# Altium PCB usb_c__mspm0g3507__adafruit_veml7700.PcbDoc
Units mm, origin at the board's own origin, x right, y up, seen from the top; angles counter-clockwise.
Board outline 92 x 60 mm, 2 copper layers (Top, Bottom), stack 0 mm thick; 33 components, 29 nets, 178 pads, 49 vias.
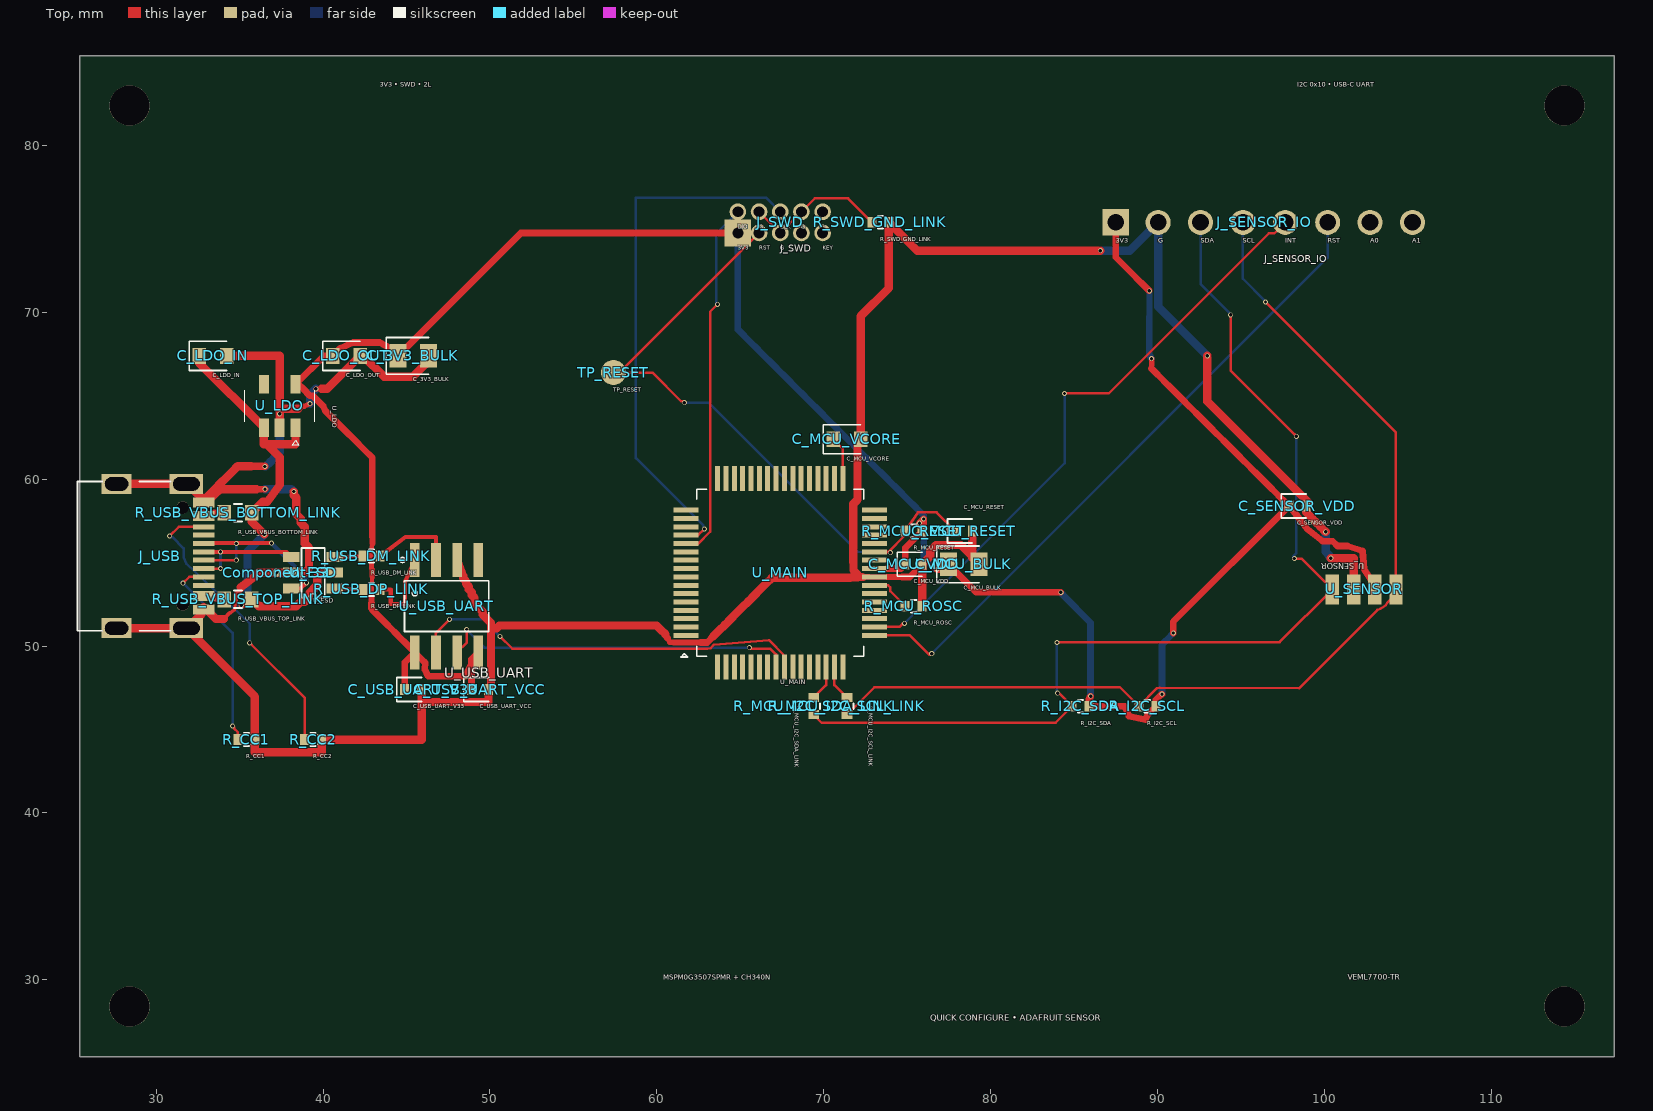
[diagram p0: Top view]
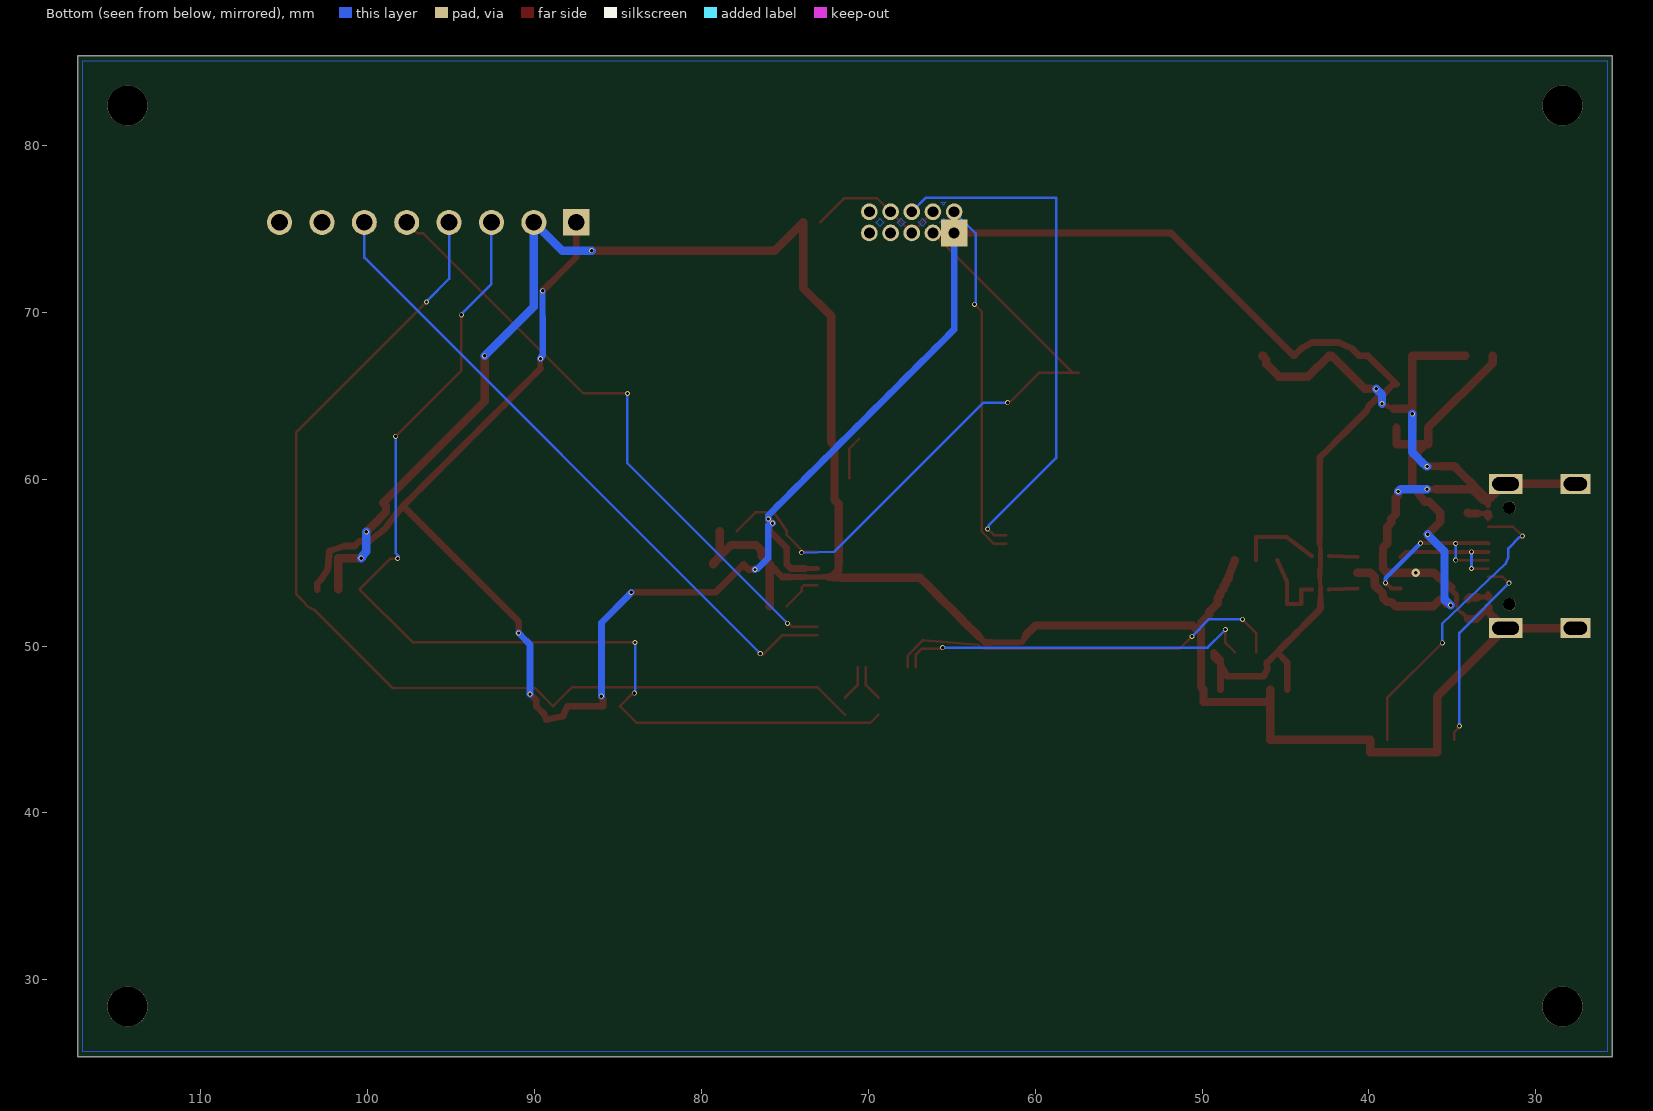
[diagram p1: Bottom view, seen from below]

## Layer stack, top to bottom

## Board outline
25.4,85.4 117.4,85.4 117.4,25.4 25.4,25.4

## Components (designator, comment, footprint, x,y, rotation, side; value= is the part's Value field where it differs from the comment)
C_3V3_BULK "" TSCIRCUIT-2.8500x1.4000mm 45.4,67.4 r0 top
C_LDO_IN "" TSCIRCUIT-2.4500x0.9500mm 33.4,67.4 r0 top
C_LDO_OUT "" TSCIRCUIT-2.4500x0.9500mm 41.4,67.4 r0 top
C_MCU_BULK "" TSCIRCUIT-2.8500x1.4000mm 78.4,54.9 r0 top
C_MCU_RESET "" TSCIRCUIT-1.5600x0.6400mm 78.4,56.9 r0 top
C_MCU_VCORE "" TSCIRCUIT-2.4500x0.9500mm 71.4,62.4 r0 top
C_MCU_VDD "" TSCIRCUIT-1.5600x0.6400mm 75.4,54.9 r0 top
C_SENSOR_VDD "" TSCIRCUIT-1.5600x0.6400mm 98.4,58.4 r0 top
C_USB_UART_V33 "" TSCIRCUIT-1.5600x0.6400mm 45.4,47.4 r0 top
C_USB_UART_VCC "" TSCIRCUIT-1.5600x0.6400mm 49.4,47.4 r0 top
Component-33 "" TSCIRCUIT-0.5000x0.5000mm 37.2,54.4 r0 top
J_SENSOR_IO "" TSCIRCUIT-19.2800x1.5000mm 96.4,75.4 r0 top
J_SWD "" TSCIRCUIT-6.0800x2.2700mm 67.4,75.4 r0 top
J_USB "" TSCIRCUIT-6.7732x9.8502mm 30.113,55.4 r90 top
R_CC1 "" TSCIRCUIT-1.5600x0.6400mm 35.4,44.4 r0 top
R_CC2 "" TSCIRCUIT-1.5600x0.6400mm 39.4,44.4 r0 top
R_I2C_SCL "" TSCIRCUIT-1.5600x0.6400mm 89.4,46.4 r0 top
R_I2C_SDA "" TSCIRCUIT-1.5600x0.6400mm 85.4,46.4 r0 top
R_MCU_I2C_SCL_LINK "" TSCIRCUIT-0.6400x1.5600mm 71.4,46.4 r270 top
R_MCU_I2C_SDA_LINK "" TSCIRCUIT-0.6400x1.5600mm 69.4,46.4 r270 top
R_MCU_RESET "" TSCIRCUIT-1.5600x0.6400mm 75.4,56.9 r0 top
R_MCU_ROSC "" TSCIRCUIT-1.5600x0.6400mm 75.4,52.4 r0 top
R_SWD_GND_LINK "" TSCIRCUIT-1.5600x0.6400mm 73.4,75.4 r0 top
R_USB_DM_LINK "" TSCIRCUIT-1.5600x0.6400mm 42.9,55.4 r0 top
R_USB_DP_LINK "" TSCIRCUIT-1.5600x0.6400mm 42.9,53.4 r0 top
R_USB_VBUS_BOTTOM_LINK "" TSCIRCUIT-2.4500x0.9500mm 34.9,58 r0 top
R_USB_VBUS_TOP_LINK "" TSCIRCUIT-2.4500x0.9500mm 34.9,52.8 r0 top
TP_RESET "" TSCIRCUIT-1.5000x1.5000mm 57.4,66.4 r0 top
U_ESD "" TSCIRCUIT-3.6000x2.5000mm 39.4,54.4 r0 top
U_LDO "" TSCIRCUIT-2.5000x3.7000mm 37.4,64.4 r270 top
U_MAIN "" TSCIRCUIT-12.8000x12.8000mm 67.4,54.4 r0 top
U_SENSOR "" TSCIRCUIT-4.6100x1.8000mm 102.4,53.4 r0 top
U_USB_UART "" TSCIRCUIT-4.3840x7.5712mm 47.4,52.4 r0 top

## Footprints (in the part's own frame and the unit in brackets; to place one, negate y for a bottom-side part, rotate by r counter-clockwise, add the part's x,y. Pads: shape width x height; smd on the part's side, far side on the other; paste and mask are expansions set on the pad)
TSCIRCUIT-0.5000x0.5000mm [mm]
TSCIRCUIT-0.6400x1.5600mm [mm]
  rect 0.54x0.64 smd: 1(-0.51,0) 2(0.51,0)
  silkscreen extent -0.15,-0.38 0.15,0.38
TSCIRCUIT-1.5000x1.5000mm [mm]
  round 1.5 smd: 1(0,0)
TSCIRCUIT-1.5600x0.6400mm [mm]
  rect 0.54x0.64 smd: 1(-0.51,0) 2(0.51,0)
  silkscreen extent -0.98,-0.72 0.51,0.72
TSCIRCUIT-2.4500x0.9500mm [mm]
  rect 0.8x0.95 smd: 1(-0.825,0) 2(0.825,0)
  silkscreen extent -1.42,-0.87 0.82,0.87
TSCIRCUIT-2.5000x3.7000mm [mm]
  rect 1.1x0.6 smd: 1(1.3,0.95) 2(1.3,0) 3(1.3,-0.95) 4(-1.3,-0.95) 5(-1.3,0.95)
  silkscreen extent -0.95,-2.1 2.35,2.1
TSCIRCUIT-2.8500x1.4000mm [mm]
  rect 1.025x1.4 smd: 1(-0.913,0) 2(0.913,0)
  silkscreen extent -1.63,-1.1 0.91,1.1
TSCIRCUIT-3.6000x2.5000mm [mm]
  rect 1x0.6 smd: 1(-1.3,-0.95) 2(-1.3,0) 3(-1.3,0.95) 4(1.3,0.95) 5(1.3,0) 6(1.3,-0.95)
  silkscreen extent -0.7,-1.49 0.7,1.49
TSCIRCUIT-4.3840x7.5712mm [mm]
  rect 0.574x2.036 smd: 1(-1.905,2.768) 2(-0.635,2.768) 3(0.635,2.768) 4(1.905,2.768) 5(1.905,-2.768) 6(0.635,-2.768) 7(-0.635,-2.768) 8(-1.905,-2.768)
  silkscreen extent -2.79,-1.52 2.53,2.92
TSCIRCUIT-4.6100x1.8000mm [mm]
  rect 0.8x1.8 smd: 1(1.905,0) 2(0.635,0) 3(-0.635,0) 4(-1.905,0)
TSCIRCUIT-6.0800x2.2700mm [mm]
  rect 1.6x1.6 hole 0.65: 1(-2.54,-0.635)
  round 1 hole 0.65: 2(-2.54,0.635) 3(-1.27,0.635) 4(0,0.635) 5(1.27,0.635) 6(2.54,0.635) 7(2.54,-0.635) 8(1.27,-0.635) 9(0,-0.635) 10(-1.27,-0.635)
TSCIRCUIT-6.7732x9.8502mm [mm]
  rect 0.3x1.3 smd: 1(-3.35,-2.737) 2(-3.05,-2.737) 3(-2.55,-2.737) 4(-2.25,-2.737) 5(-1.75,-2.737) 6(-1.25,-2.737) 7(-0.75,-2.737) 8(-0.25,-2.737) 9(0.25,-2.737) 10(0.75,-2.737) 11(1.25,-2.737) 12(1.75,-2.737) 13(2.55,-2.737) 14(2.25,-2.737) 15(3.35,-2.737) 16(3.05,-2.737)
  rect 1.2x2 hole 0.8 slot 1.6 at 90 deg: 17(-4.325,-1.693) 18(4.325,-1.693)
  rect 1.2x1.8 hole 0.8 slot 1.4 at 90 deg: 19(4.325,2.487) 20(-4.325,2.487)
  round 0.75 hole 0.75 unplated: NPTH-1(-2.9,-1.468) NPTH-2(2.9,-1.468)
  silkscreen extent -4.47,-0.75 4.47,4.83
TSCIRCUIT-12.8000x12.8000mm [mm]
  rect 1.5x0.3 smd: 1(-5.65,-3.75) 2(-5.65,-3.25) 3(-5.65,-2.75) 4(-5.65,-2.25) 5(-5.65,-1.75) 6(-5.65,-1.25) 7(-5.65,-0.75) 8(-5.65,-0.25) 9(-5.65,0.25) 10(-5.65,0.75) 11(-5.65,1.25) 12(-5.65,1.75) 13(-5.65,2.25) 14(-5.65,2.75) 15(-5.65,3.25) 16(-5.65,3.75) 33(5.65,3.75) 34(5.65,3.25) 35(5.65,2.75) 36(5.65,2.25) 37(5.65,1.75) 38(5.65,1.25) 39(5.65,0.75) 40(5.65,0.25) 41(5.65,-0.25) 42(5.65,-0.75) 43(5.65,-1.25) 44(5.65,-1.75) 45(5.65,-2.25) 46(5.65,-2.75) 47(5.65,-3.25) 48(5.65,-3.75)
  rect 0.3x1.5 smd: 17(-3.75,5.65) 18(-3.25,5.65) 19(-2.75,5.65) 20(-2.25,5.65) 21(-1.75,5.65) 22(-1.25,5.65) 23(-0.75,5.65) 24(-0.25,5.65) 25(0.25,5.65) 26(0.75,5.65) 27(1.25,5.65) 28(1.75,5.65) 29(2.25,5.65) 30(2.75,5.65) 31(3.25,5.65) 32(3.75,5.65) 49(3.75,-5.65) 50(3.25,-5.65) 51(2.75,-5.65) 52(2.25,-5.65) 53(1.75,-5.65) 54(1.25,-5.65) 55(0.75,-5.65) 56(0.25,-5.65) 57(-0.25,-5.65) 58(-0.75,-5.65) 59(-1.25,-5.65) 60(-1.75,-5.65) 61(-2.25,-5.65) 62(-2.75,-5.65) 63(-3.25,-5.65) 64(-3.75,-5.65)
  silkscreen extent -5.95,-5.05 5,5
TSCIRCUIT-19.2800x1.5000mm [mm]
  rect 1.6x1.6 hole 1: 1(-8.89,0)
  round 1.5 hole 1: 2(-6.35,0) 3(-3.81,0) 4(-1.27,0) 5(1.27,0) 6(3.81,0) 7(6.35,0) 8(8.89,0)

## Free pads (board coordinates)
  round 2.4 hole 2.4 unplated: NPTH-3(28.4,28.4) NPTH-4(114.4,28.4) NPTH-5(28.4,82.4) NPTH-6(114.4,82.4)

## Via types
v1: diameter 0.3, hole 0.2, Top to Bottom, 48 vias
v2: diameter 0.5, hole 0.2, Top to Bottom, 1 vias

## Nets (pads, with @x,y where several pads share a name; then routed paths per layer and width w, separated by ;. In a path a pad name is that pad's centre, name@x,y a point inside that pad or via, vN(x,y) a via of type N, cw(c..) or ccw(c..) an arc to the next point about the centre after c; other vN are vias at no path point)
".J_SWD > .pin2 to .U_MAIN > .pin12": J_SWD.2 U_MAIN.12 | length 21.7
  Top w0.15: U_MAIN.12 62.494,56.15 63.204,56.859 63.204,70.054 v1(63.641,70.491)
  Bottom w0.15: v1(63.641,70.491) 63.572,70.56 63.572,70.569 63.572,74.747 J_SWD.2
".J_SWD > .pin4 to .U_MAIN > .pin13": J_SWD.4 U_MAIN.13 | length 31.8
  Top w0.15: U_MAIN.13 62.479,56.65 v1(62.847,57.018)
  Bottom w0.15: v1(62.847,57.018) 62.797,57.068 62.797,57.224 58.746,61.275 58.746,76.869 66.566,76.869 J_SWD.4
".U_MAIN > .pin42 to .R_MCU_ROSC > .pin1": R_MCU_ROSC.1 U_MAIN.42 | length 2.5
  Top w0.15: U_MAIN.42 73.86,53.65 73.994,53.516 73.994,53.296 R_MCU_ROSC.1
GND: C_3V3_BULK.2 C_LDO_IN.2 C_LDO_OUT.2 C_MCU_BULK.2 C_MCU_RESET.2 C_MCU_VCORE.2 C_MCU_VDD.2 C_SENSOR_VDD.2 C_USB_UART_V33.2 C_USB_UART_VCC.2 J_SENSOR_IO.2 J_USB.1 J_USB.2 J_USB.15 J_USB.16 J_USB.17 J_USB.18 J_USB.19 J_USB.20 R_CC1.2 R_CC2.2 R_MCU_ROSC.2 R_SWD_GND_LINK.2 U_ESD.2 U_LDO.2 U_MAIN.41 U_SENSOR.3 U_USB_UART.3 | length 208
  Top w0.2: 34.4,51.977 34.7,52.2 34.749,52.692
  Top w0.25: 34.055,51.627 34.4,51.977
  Top w0.275: J_USB.2 J_USB.1@33.09,52.109
  Top w0.3: J_USB.1@32.699,51.9 J_USB.1 J_USB.1@32.849,52.2 ; J_USB.15@32.699,58.9 J_USB.15 ; J_USB.16 J_USB.16@32.999,58.6 ; J_USB.16@32.849,58.6 J_USB.15 ; J_USB.15@32.999,58.9 J_USB.15 ; 34.749,52.692 34.754,53.057 ; v1(39.568,65.421) 39.907,65.421 ; U_MAIN.41@72.675,54.15 72.769,54.15 72.863,54.15 72.956,54.15 U_MAIN.41 ; U_MAIN.41@72.712,54.16 U_MAIN.41 ; U_MAIN.41@73.8,54.15 73.706,54.15 73.612,54.15 73.519,54.15 73.425,54.15 73.331,54.15 73.237,54.15 73.144,54.15 U_MAIN.41
  Top w0.312: 34.754,53.057 35.09,53.392 35.072,53.525 ; 38.513,64.225 38.866,64.38 v1(39.219,64.535)
  Top w0.325: J_USB.16 J_USB.16@32.849,58.6 ; J_USB.16@32.999,58.6 J_USB.15@33.168,58.769 ; 60.642,50.48 60.775,50.244 61.002,50.224
  Top w0.329: 72.3,54.157 72.402,54.155 U_MAIN.41@72.675,54.15
  Top w0.346: U_MAIN.41@72.386,54.129 U_MAIN.41@72.712,54.16
  Top w0.35: 61.002,50.224 61.407,50.224 61.811,50.224 62.215,50.224 62.619,50.224
  Top w0.375: U_MAIN.41@73.8,54.15 74.253,54.15 74.707,54.15
  Top w0.4: 36.012,59.405 36.453,59.405 36.516,59.408 v1(36.517,59.41) ; 37.2,54.4 U_ESD.2@37.6,54.4 ; 62.619,50.224 63.024,50.224 63.376,50.576 ; 74.707,54.15 75.16,54.15 75.41,54.4 75.66,54.65 C_MCU_VDD.2
  Top w0.425: 60.509,50.717 60.642,50.48
  Top w0.437: 71.59,54.097 72.059,54.097 U_MAIN.41@72.386,54.129
  Top w0.45: 35.695,60.776 36.102,60.772 v1(36.509,60.769)
  Top w0.475: 33.572,51.627 34.055,51.627 ; 72.129,54.16 72.3,54.157
  Top w0.5: J_USB.20 J_USB.17 ; J_USB.19 J_USB.18 31.874,59.725 32.474,59.125 32.699,58.9 ; 32.699,51.9 32.474,51.675 31.874,51.075 J_USB.17 ; J_USB.1@32.849,52.2 J_USB.2 ; 32.999,58.9 33.188,59.089 33.527,59.428 33.866,59.767 34.204,60.105 34.543,60.444 34.882,60.783 35.289,60.779 35.695,60.776 ; J_USB.1@33.09,52.109 33.572,51.627 ; J_USB.15@33.168,58.769 33.486,59.087 33.805,59.405 34.246,59.405 34.687,59.405 35.129,59.405 35.57,59.405 36.012,59.405 ; C_LDO_IN.2 37.4,67.4 U_LDO.2 ; 35.072,53.525 35.418,53.795 35.763,54.064 36.1,54.4 36.467,54.4 36.833,54.4 37.2,54.4 38.9,54.4 39.15,54.65 39.15,55.9 38.9,56.15 38.9,57.15 38.65,57.4 38.65,57.65 38.4,57.9 38.4,58.9 38.248,59.052 v1(38.248,59.274) ; v1(37.4,63.925) 37.4,62.85 U_LDO.2 ; 38.513,64.225 37.4,64.225 U_LDO.2 ; 39.907,65.421 40.246,65.421 40.576,65.751 40.906,66.081 41.236,66.41 41.565,66.74 41.895,67.07 C_LDO_OUT.2 42.4,67.4 43.65,66.15 45.4,66.15 46.15,66.9 46.15,67.15 46.4,67.4 C_3V3_BULK.2 ; U_USB_UART.3 48.4,54.2 48.4,54.067 48.567,53.9 48.567,53.733 48.733,53.567 48.733,53.4 48.9,53.233 48.9,53.067 49.067,52.9 49.067,52.567 49.567,52.067 49.567,51.9 50.067,51.4 C_USB_UART_VCC.2@50.067,47.567 ; 60.509,50.717 60.262,50.964 59.993,51.233 50.567,51.233 50.4,51.067 50.233,51.067 50.067,50.9 C_USB_UART_VCC.2@50.067,47.567 ; 63.376,50.576 63.728,50.928 64.08,51.28 64.432,51.632 64.784,51.984 65.137,52.337 65.489,52.689 65.841,53.041 66.193,53.393 66.545,53.745 66.897,54.097 67.367,54.097 67.836,54.097 68.305,54.097 68.774,54.097 69.243,54.097 69.713,54.097 70.182,54.097 70.651,54.097 71.12,54.097 71.59,54.097 ; 72.129,54.16 71.957,54.351 71.786,54.541 71.787,55.037 71.775,55.025 71.775,58.525 72.025,58.775 72.025,62.025 72.225,62.225 C_MCU_VCORE.2 72.225,62.892 72.225,63.384 72.225,63.876 72.225,64.368 72.225,64.86 72.225,65.352 72.225,65.844 72.225,66.336 72.225,66.828 72.225,67.32 72.225,67.812 72.225,68.303 72.225,68.795 72.225,69.287 72.225,69.779 73.91,71.464 R_SWD_GND_LINK.2 75.608,73.702 v1(86.586,73.702) ; R_MCU_ROSC.2 C_MCU_VDD.2 75.9,54.9 76.4,55.4 76.4,55.733 76.733,56.067 78.233,56.067 79.313,54.988 C_MCU_BULK.2 78.91,55.303 C_MCU_RESET.2 ; v1(92.997,67.4) 92.997,64.667 94.565,63.098 99.087,58.577 C_SENSOR_VDD.2 98.91,58.03 99.198,57.742 99.486,57.454 99.774,57.166 100.062,56.878 v1(100.086,56.854) ; v1(100.398,55.276) 101.765,55.276 U_SENSOR.3 ; J_USB.17 35.91,46.971 R_CC1.2 35.91,43.65 39.91,43.65 R_CC2.2 40.41,44.4 40.91,44.4 45.91,44.4 C_USB_UART_V33.2 45.91,46.65 49.91,46.65 C_USB_UART_VCC.2 ; C_USB_UART_VCC.2 C_USB_UART_VCC.2@49.91,47.41 ; C_USB_UART_VCC.2 C_USB_UART_VCC.2@49.91,47.41 ; C_USB_UART_VCC.2@49.91,47.41 C_USB_UART_VCC.2@50.067,47.567 ; C_USB_UART_VCC.2@49.91,47.41 C_USB_UART_VCC.2@50.067,47.567
  Bottom w0.5: v1(36.509,60.769) 36.543,60.763 36.551,60.763 36.834,61.046 37.117,61.329 37.4,61.612 37.4,61.951 37.4,62.29 v1(37.4,63.925) ; v1(36.517,59.41) 36.913,59.409 37.308,59.408 37.704,59.408 38.1,59.407 38.219,59.287 38.235,59.287 v1(38.248,59.274) ; v1(39.219,64.535) 39.219,64.804 39.219,65.072 39.544,65.397 v1(39.568,65.421) ; v1(86.586,73.702) 88.352,73.702 J_SENSOR_IO.2 90.05,74.941 90.05,74.481 90.05,74.022 90.05,73.563 90.05,73.103 90.05,72.644 90.05,72.184 90.05,71.725 90.05,71.266 90.05,70.806 90.05,70.347 90.377,70.02 90.705,69.692 91.032,69.365 91.36,69.037 91.687,68.71 92.015,68.382 92.342,68.055 92.669,67.728 v1(92.997,67.4) ; v1(100.086,56.854) 100.086,56.457 100.086,56.061 100.086,55.664 100.305,55.446 100.305,55.369 v1(100.398,55.276)
MAIN_RESET: C_MCU_RESET.1 J_SWD.10 R_MCU_RESET.1 TP_RESET.1 U_MAIN.38 | length 40.8
  Top w0.15: v1(61.65,64.593) 61.562,64.681 61.452,64.681 59.733,66.4 TP_RESET.1 57.765,66.4 J_SWD.10 ; v1(74,55.6) U_MAIN.38 73.889,55.65 74.889,56.651 R_MCU_RESET.1@74.889,56.899 ; R_MCU_RESET.1 75.65,58.014 76.776,58.014 C_MCU_RESET.1
  Bottom w0.15: v1(61.65,64.593) 63.11,64.593 72.053,55.65 v1(74,55.6)
MCU_I2C_SCL_LOCAL: R_MCU_I2C_SCL_LINK.1 U_MAIN.50 | length 2.2
  Top w0.15: U_MAIN.50 70.65,47.66 R_MCU_I2C_SCL_LINK.1
MCU_I2C_SDA_LOCAL: R_MCU_I2C_SDA_LINK.1 U_MAIN.51 | length 2.2
  Top w0.15: R_MCU_I2C_SDA_LINK.1 70.15,47.66 U_MAIN.51
MSPM0_VCORE: C_MCU_VCORE.1 U_MAIN.32 | length 2.6
  Top w0.15: C_MCU_VCORE.1 71.15,61.825 U_MAIN.32
SENSOR_ADDR0: J_SENSOR_IO.7
SENSOR_ADDR1: J_SENSOR_IO.8
SENSOR_INT: J_SENSOR_IO.5 U_MAIN.47 | length 37.1
  Top w0.15: U_MAIN.47 74.548,51.15 74.726,51.328 74.804,51.328 v1(74.847,51.371) ; v1(84.441,65.147) 87.09,65.149 96.692,74.748 97.018,74.748 J_SENSOR_IO.5
  Bottom w0.15: v1(74.847,51.371) 84.439,60.963 v1(84.441,65.147) v1(84.441,65.147)
SENSOR_RESET: J_SENSOR_IO.6 U_MAIN.48 | length 39.6
  Top w0.15: U_MAIN.48 75.165,50.65 76.321,49.494 76.42,49.494 v1(76.48,49.554)
  Bottom w0.15: v1(76.48,49.554) 100.21,73.284 J_SENSOR_IO.6
SENSOR_SCL: J_SENSOR_IO.4 R_I2C_SCL.1 R_MCU_I2C_SCL_LINK.2 U_SENSOR.1 | length 62.9
  Top w0.15: R_MCU_I2C_SCL_LINK.2 73.047,47.537 87.611,47.537 87.753,47.537 R_I2C_SCL.1 89.981,47.491 90.132,47.509 98.516,47.491 103.194,52.168 103.37,52.241 103.705,52.439 103.788,52.614 104.305,53.132 U_SENSOR.1 104.305,62.805 v1(96.485,70.625)
  Bottom w0.15: J_SENSOR_IO.4 95.13,72.022 96.454,70.698 96.454,70.656 v1(96.485,70.625)
SENSOR_SDA: J_SENSOR_IO.3 R_I2C_SDA.1 R_MCU_I2C_SDA_LINK.2 U_SENSOR.4 | length 63.8
  Top w0.15: R_MCU_I2C_SDA_LINK.2 69.881,45.409 83.899,45.409 R_I2C_SDA.1 84.105,47.185 v1(84.022,47.185) ; v1(83.984,50.217) 84.005,50.238 84.055,50.238 97.333,50.238 U_SENSOR.4 98.646,55.249 v1(98.213,55.249) ; v1(94.394,69.855) 94.394,66.534 98.232,62.696 98.232,62.675 v1(98.332,62.574)
  Bottom w0.15: v1(83.984,50.217) 83.984,47.223 83.987,47.22 v1(84.022,47.185) ; J_SENSOR_IO.3 92.59,71.7 94.393,69.897 94.393,69.856 v1(94.394,69.855) ; v1(98.213,55.249) 98.154,55.308 98.154,55.401 98.332,55.579 v1(98.332,62.574)
swd-ground-1-to-2: J_SWD.3 J_SWD.5 J_SWD.9 R_SWD_GND_LINK.1 | length 8.8
  Top w0.15: J_SWD.3 J_SWD.9 J_SWD.5 69.481,76.846 71.471,76.846 71.471,76.819 R_SWD_GND_LINK.1
UART_MSP_RX: U_MAIN.57 U_USB_UART.6 | length 21.5
  Top w0.15: U_USB_UART.6 48.6,50.197 v1(48.6,51) ; v1(65.55,49.909) 65.552,49.907 65.569,49.907 65.622,49.853 66.797,49.853 67.15,49.5 U_MAIN.57
  Bottom w0.15: v1(48.6,51) 48.684,50.916 48.684,50.893 49.668,49.909 v1(65.55,49.909)
UART_MSP_TX: U_MAIN.56 U_USB_UART.7 | length 24.3
  Top w0.15: U_USB_UART.7 46.765,50.794 v1(47.579,51.608) ; v1(50.603,50.587) 50.612,50.578 51.347,49.843 63.025,49.843 63.221,49.873 63.428,50.096 66.714,50.362 67.65,49.427 U_MAIN.56
  Bottom w0.15: v1(47.579,51.608) 47.588,51.617 47.781,51.617 49.573,51.617 v1(50.603,50.587)
usb-dm-device: R_USB_DM_LINK.1 U_ESD.4 | length 1.7
  Top w0.25: U_ESD.4 R_USB_DM_LINK.1
usb-dm-port-tie: J_USB.7 J_USB.9 U_ESD.3 | length 8.4
  Top w0.15: J_USB.7 v1(33.85,54.65) ; J_USB.9 v1(33.85,55.65)
  Top w0.25: J_USB.9 34.67,55.65 37.8,55.65 U_ESD.3
  Bottom w0.15: v1(33.85,54.65) v1(33.85,55.65)
usb-dm-uart: R_USB_DM_LINK.2 U_USB_UART.2 | length 5.1
  Top w0.25: R_USB_DM_LINK.2 44.95,56.55 46.765,56.55 U_USB_UART.2
usb-dp-device: R_USB_DP_LINK.1 U_ESD.6 | length 1.7
  Top w0.25: U_ESD.6 R_USB_DP_LINK.1
usb-dp-port-tie: J_USB.8 J_USB.10 U_ESD.1 | length 13.3
  Top w0.15: J_USB.8 v1(34.8,55.15) ; J_USB.10 v1(34.8,56.15)
  Top w0.25: J_USB.10 32.874,56.175 v1(36.91,56.175) ; U_ESD.1 38.647,53.45 38.967,53.77 38.97,53.77 v1(39,53.8)
  Bottom w0.15: v1(34.8,55.15) v1(34.8,56.15)
  Bottom w0.25: v1(36.91,56.175) 36.899,56.169 39,54.068 v1(39,53.8)
usb-dp-uart: R_USB_DP_LINK.2 U_USB_UART.1 | length 5.1
  Top w0.25: R_USB_DP_LINK.2 44.05,53.4 44.05,52.53 44.9,52.53 44.9,53.85 U_USB_UART.1
USB_CC1: J_USB.6 R_CC1.1 | length 12.3
  Top w0.15: v1(31.606,53.779) 31.978,54.15 J_USB.6 ; v1(34.58,45.219) 34.671,45.128 34.671,45.059 34.89,44.84 R_CC1.1
  Bottom w0.15: v1(31.606,53.779) 31.539,53.846 31.535,53.846 34.58,50.801 v1(34.58,45.219)
USB_CC2: J_USB.12 R_CC2.1 | length 17.9
  Top w0.15: v1(30.8,56.6) 31.35,57.15 J_USB.12 ; v1(35.6,50.2) 35.715,50.085 38.89,46.91 R_CC2.1
  Bottom w0.15: v1(30.8,56.6) 30.868,56.532 30.975,56.532 31.643,55.864 31.643,55.31 31.8,54.95 35.6,51.352 v1(35.6,50.2)
USB_VBUS_BOTTOM_LOCAL: J_USB.13 J_USB.14 R_USB_VBUS_BOTTOM_LINK.1 | length 1.5
  Top w0.3: J_USB.14 J_USB.14@32.849,57.8 ; J_USB.13 32.927,57.95 33.005,57.95 33.083,57.95 33.161,57.95 33.239,57.95 33.317,57.95 33.394,57.95 33.472,57.95 33.499,57.95
  Top w0.475: J_USB.13@32.849,57.8 J_USB.13 ; 33.499,57.95 R_USB_VBUS_BOTTOM_LINK.1@33.762,57.95
  Top w0.5: R_USB_VBUS_BOTTOM_LINK.1@33.762,57.95 34.025,57.95 R_USB_VBUS_BOTTOM_LINK.1
USB_VBUS_TOP_LOCAL: J_USB.3 J_USB.4 R_USB_VBUS_TOP_LINK.1 | length 1.6
  Top w0.3: J_USB.4 32.849,53 J_USB.3 32.944,52.958 33.032,52.939 33.499,52.939
  Top w0.5: 33.499,52.939 33.675,52.939 33.936,52.939 R_USB_VBUS_TOP_LINK.1
VBUS5: C_LDO_IN.1 R_USB_VBUS_BOTTOM_LINK.2 R_USB_VBUS_TOP_LINK.2 U_ESD.5 U_LDO.1 U_LDO.3 | length 30
  Top w0.325: v1(35.099,52.457) 35.382,52.457 R_USB_VBUS_TOP_LINK.2
  Top w0.5: C_LDO_IN.1 32.575,66.975 U_LDO.3 ; R_USB_VBUS_TOP_LINK.2 35.981,52.544 35.9,52.625 35.9,52.65 36.15,52.4 38.4,52.4 38.65,52.65 38.9,52.65 39.15,52.9 39.15,53.15 39.65,53.65 39.65,54.15 39.9,54.4 U_ESD.5 ; v1(36.48,56.698) 35.725,57.453 R_USB_VBUS_BOTTOM_LINK.2 36.375,58.65 36.65,58.65 37.397,59.665 37.397,61.329 36.454,62.272 36.452,62.686 U_LDO.3 ; U_LDO.1 38.35,62.1 36.45,62.1 U_LDO.3
  Bottom w0.5: v1(35.099,52.457) 35.387,52.745 35.468,52.745 35.468,55.686 v1(36.48,56.698)
VCC_3V3: C_3V3_BULK.1 C_LDO_OUT.1 C_MCU_BULK.1 C_MCU_VDD.1 C_SENSOR_VDD.1 C_USB_UART_V33.1 C_USB_UART_VCC.1 J_SENSOR_IO.1 J_SWD.1 R_I2C_SCL.2 R_I2C_SDA.2 R_MCU_RESET.2 U_LDO.5 U_MAIN.40 U_SENSOR.2 U_USB_UART.5 U_USB_UART.8 | length 157.2
  Top w0.25: 42.9,53.525 42.924,53.86 42.949,54.194
  Top w0.262: 42.9,55.65 42.925,55.907 42.95,56.163
  Top w0.275: 42.9,52.9 42.9,53.212 42.9,53.525 ; 42.9,54.983 42.9,55.317 42.9,55.65
  Top w0.3: U_MAIN.40 73.15,54.65 73.25,54.65 73.35,54.65 73.45,54.65 73.55,54.65 73.65,54.65 73.75,54.65 U_MAIN.40@73.8,54.65
  Top w0.312: 42.9,54.983 42.9,54.65 42.949,54.588 42.949,54.194
  Top w0.325: 89.653,66.637 89.654,66.934 v1(89.655,67.232)
  Top w0.363: 42.95,56.163 42.951,56.557
  Top w0.387: 42.9,52.587 42.9,52.9
  Top w0.4: 42.9,52.587 42.9,52.275 42.947,52.225 42.958,52.169 43.24,51.887 43.522,51.605 43.804,51.323 44.086,51.041 44.368,50.759 44.649,50.478 44.931,50.196 45.213,49.914 U_USB_UART.8 ; 42.951,56.557 42.951,56.951 42.951,57.345 42.952,57.739 42.952,58.133 42.952,58.527 42.953,58.921 42.953,59.314 42.953,59.708 42.954,60.102 42.954,60.496 42.954,60.89 42.955,61.284 42.824,61.418 42.556,61.686 42.289,61.953 42.021,62.221 41.754,62.489 41.486,62.756 41.218,63.024 40.951,63.291 40.683,63.559 40.416,63.827 40.148,64.094 40,64.4 39.4,65 39.2,65 38.81,65.432 38.542,65.7 U_LDO.5 40.05,67.4 C_LDO_OUT.1 40.795,67.622 41.016,67.843 41.8,68.2 43.4,68.2 44.047,67.841 44.267,67.62 C_3V3_BULK.1 51.853,74.765 J_SWD.1 ; C_USB_UART_V33.1 44.89,49.027 U_USB_UART.8 ; C_USB_UART_VCC.1 48.89,49.217 U_USB_UART.5 49.305,49.345 49.093,49.129 48.881,48.912 48.5,48.2 46.3,48.2 46.1,48.6 46.115,49.012 45.908,49.219 45.702,49.425 U_USB_UART.8 ; U_MAIN.40@73.8,54.65 73.85,54.65 74.64,54.65 C_MCU_VDD.1 74.89,55.88 R_MCU_RESET.2 ; v1(75.75,57.375) 75.994,57.614 75.91,57.53 75.91,57.215 R_MCU_RESET.2 ; v1(76,57.62) 76,57.305 76,56.99 R_MCU_RESET.2 ; v1(76.791,54.592) 77.18,54.592 77.334,54.746 C_MCU_BULK.1 79.162,53.226 v1(84.215,53.226) ; v1(86,47) 85.96,46.96 85.96,46.879 85.91,46.829 R_I2C_SDA.2 86.264,46.4 86.619,46.4 86.973,46.4 87.327,46.4 87.682,46.4 88.036,46.4 88.3,45.8 89.3,45.6 89.482,45.972 ; J_SENSOR_IO.1 87.51,75.051 87.51,74.702 87.51,74.353 87.51,74.005 87.51,73.656 87.51,73.307 87.778,73.038 88.047,72.77 88.315,72.502 88.583,72.233 88.852,71.965 89.12,71.697 89.389,71.428 v1(89.523,71.294) ; 89.653,66.637 89.928,66.362 90.202,66.088 90.477,65.813 90.751,65.539 91.026,65.264 91.3,64.99 91.575,64.715 91.85,64.44 92.124,64.166 92.399,63.891 92.673,63.617 92.948,63.342 93.222,63.068 93.497,62.793 93.771,62.519 94.046,62.244 94.321,61.969 94.595,61.695 94.87,61.42 95.144,61.146 95.419,60.871 95.693,60.597 95.968,60.322 96.243,60.047 96.517,59.773 96.792,59.498 97.066,59.224 97.341,58.949 97.615,58.675 C_SENSOR_VDD.1 ; v1(90.276,47.119) 90.177,47.039 89.91,46.772 R_I2C_SCL.2 89.696,46.186 89.482,45.972 ; v1(90.958,50.79) 90.958,51.468 C_SENSOR_VDD.1 ; U_SENSOR.2 103.035,53.768 102.755,54.048 102.4,54.6 102.3,55.7 101.4,56 100.795,56.008 100.515,56.288 100.258,56.288 99.9,56.3 99,57 98.238,57.99 98.064,58.195 C_SENSOR_VDD.1 ; 89.482,45.972 89.474,45.972 89.482,45.972
  Bottom w0.35: 89.523,69.747 89.523,70.134 89.523,70.52 89.523,70.907 v1(89.523,71.294)
  Bottom w0.4: J_SWD.1 64.86,74.379 64.86,73.993 64.86,73.608 64.86,73.222 64.86,72.836 64.86,72.45 64.86,72.065 64.86,71.679 64.86,71.293 64.86,70.907 64.86,70.521 64.86,70.136 64.86,69.75 64.86,69.364 64.86,68.978 65.138,68.7 65.417,68.421 65.695,68.143 65.974,67.864 66.252,67.586 66.531,67.308 66.809,67.029 67.088,66.751 67.366,66.472 67.644,66.194 67.923,65.915 68.201,65.637 68.48,65.358 68.758,65.08 69.037,64.802 69.315,64.523 69.594,64.245 69.872,63.966 70.151,63.688 70.429,63.409 70.707,63.131 70.986,62.852 71.264,62.574 71.543,62.295 71.821,62.017 72.1,61.739 72.378,61.46 72.657,61.182 72.935,60.903 73.213,60.625 73.492,60.346 73.77,60.068 74.049,59.789 74.327,59.511 74.606,59.233 74.884,58.954 75.163,58.676 75.441,58.397 75.719,58.119 75.998,57.84 75.998,57.622 v1(76,57.62) ; v1(75.75,57.375) 76,57.23 76,56.84 76,56.45 76,56.06 76,55.67 76,55.28 76.214,55.066 76.428,54.851 76.643,54.637 76.745,54.637 v1(76.791,54.592) ; v1(84.215,53.226) 84.341,53.1 84.341,53.062 86,51.402 v1(86,47) ; 89.523,69.747 89.523,69.36 89.523,68.973 89.523,68.587 89.523,68.2 89.523,67.813 89.523,67.426 89.616,67.333 89.616,67.271 v1(89.655,67.232) ; v1(90.276,47.119) 90.276,50.096 90.835,50.655 90.835,50.667 v1(90.958,50.79)
pads on no net: J_SWD.6 J_SWD.7 J_SWD.8 J_USB.5 J_USB.11 J_USB.NPTH-1 J_USB.NPTH-2 U_LDO.4 U_MAIN.1 U_MAIN.2 U_MAIN.3 U_MAIN.4 U_MAIN.5 U_MAIN.6 U_MAIN.7 U_MAIN.8 U_MAIN.9 U_MAIN.10 U_MAIN.11 U_MAIN.14 U_MAIN.15 U_MAIN.16 U_MAIN.17 U_MAIN.18 U_MAIN.19 U_MAIN.20 U_MAIN.21 U_MAIN.22 U_MAIN.23 U_MAIN.24 U_MAIN.25 U_MAIN.26 U_MAIN.27 U_MAIN.28 U_MAIN.29 U_MAIN.30 U_MAIN.31 U_MAIN.33 U_MAIN.34 U_MAIN.35 U_MAIN.36 U_MAIN.37 U_MAIN.39 U_MAIN.43 U_MAIN.44 U_MAIN.45 U_MAIN.46 U_MAIN.49 U_MAIN.52 U_MAIN.53 U_MAIN.54 U_MAIN.55 U_MAIN.58 U_MAIN.59 U_MAIN.60 U_MAIN.61 U_MAIN.62 U_MAIN.63 U_MAIN.64 U_USB_UART.4
copper on no net:
  other v2: 37.2,54.4

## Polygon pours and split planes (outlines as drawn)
GND on Bottom (solid): 117.1,85.1 25.7,85.1 25.7,25.7 117.1,25.7
GND on Bottom (solid): 65.635,76.594 65.355,76.594 65.39,76.565 65.484,76.452 65.495,76.43 65.506,76.452 65.6,76.565
GND on Bottom (solid): 65.495,75.64 65.484,75.618 65.399,75.515 65.591,75.515 65.506,75.618
GND on Bottom (solid): 65.61,75.496 65.61,75.304 65.713,75.389 65.735,75.4 65.713,75.411
GND on Bottom (solid): 69.305,75.64 69.294,75.618 69.2,75.505 69.087,75.411 69.065,75.4 69.087,75.389 69.2,75.295 69.294,75.182 69.305,75.16 69.316,75.182 69.41,75.295 69.523,75.389 69.545,75.4 69.523,75.411 69.41,75.505 69.316,75.618
GND on Bottom (solid): 68.035,75.64 68.024,75.618 67.93,75.505 67.817,75.411 67.795,75.4 67.817,75.389 67.93,75.295 68.024,75.182 68.035,75.16 68.046,75.182 68.14,75.295 68.253,75.389 68.275,75.4 68.253,75.411 68.14,75.505 68.046,75.618
GND on Bottom (solid): 66.765,75.64 66.754,75.618 66.66,75.505 66.547,75.411 66.525,75.4 66.547,75.389 66.66,75.295 66.754,75.182 66.765,75.16 66.776,75.182 66.87,75.295 66.983,75.389 67.005,75.4 66.983,75.411 66.87,75.505 66.776,75.618

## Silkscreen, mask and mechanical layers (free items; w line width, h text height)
Top Overlay:
  text "3V3 • SWD • 2L" at 43.4,83.4 h0.48
  text "I2C 0x10 • USB-C UART" at 98.4,83.4 h0.5
  text "MSPM0G3507SPMR + CH340N" at 60.4,29.9 h0.52
  text "VEML7700-TR" at 101.4,29.9 h0.55
  text "QUICK CONFIGURE • ADAFRUIT SENSOR" at 76.4,27.4 h0.65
